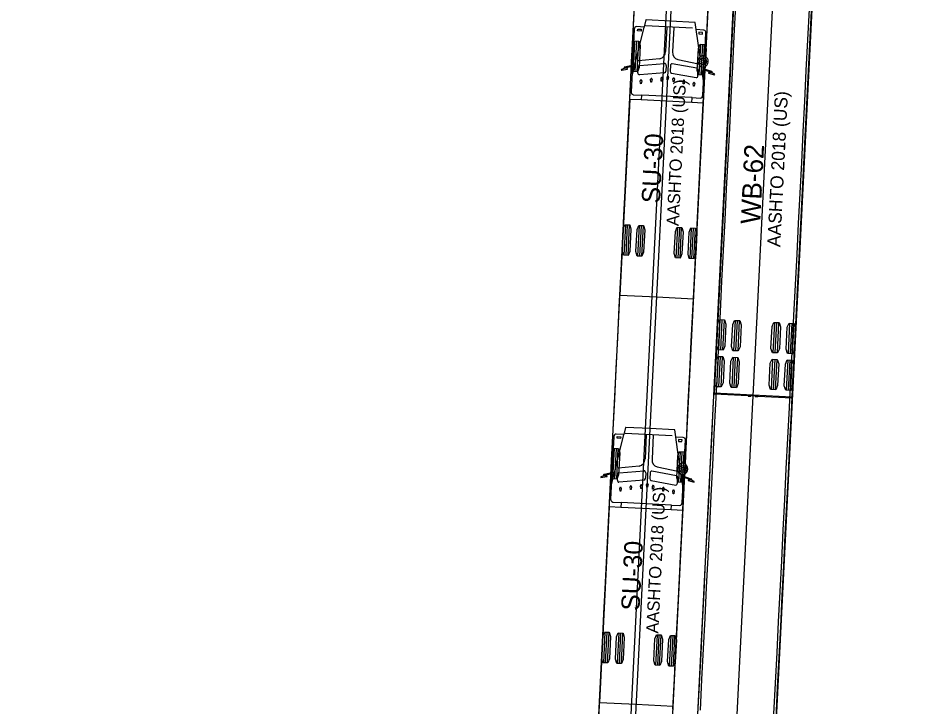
# Model space of a CAD drawing. Extents: x 260275 to 261282, y 610916 to 614143.
# Drawn here: x 260986.2 to 261084.3, y 612243.5 to 612318.4 of the extents above; entities that cross this region are included whole.
import ezdxf

# ---------------------------------------------------------------- set-up
doc = ezdxf.new("R2010")
doc.units = 0
doc.layers.add('GE_X_Alignment', color=7, linetype='Continuous')
doc.layers.add('TopoDOT_Transients', color=7, linetype='Continuous')

msp = doc.modelspace()

# ---------------------------------------------------------------- linework, layer by layer
at = {"layer": 'GE_X_Alignment'}
msp.add_line((260986.249, 610915.954), (261148.276, 614142.838), dxfattribs=at)
at = {"layer": 'TopoDOT_Transients'}
for p, q in [((261059.045, 612136.423), (261081.046, 612574.591)), ((261048.059, 612136.974), (261068.197, 612538.052)), ((261052.939, 612311.94), (261054.28, 612317.407)), ((261059.534, 612317.267), (261054.436, 612317.523)), ((261056.735, 612317.407), (261056.601, 612314.742)), ((261053.569, 612316.987), (261053.578, 612317.181)), ((261053.947, 612316.968), (261053.569, 612316.987)), ((261053.578, 612317.181), (261053.956, 612317.162)), ((261053.956, 612317.162), (261053.947, 612316.968)), ((261057.5, 612317.369), (261057.366, 612314.704)), ((261060.361, 612314.157), (261059.943, 612317.123)), ((261060.24, 612316.846), (261060.23, 612316.652)), ((261060.23, 612316.652), (261060.609, 612316.633)), ((261060.618, 612316.827), (261060.24, 612316.846)), ((261060.609, 612316.633), (261060.618, 612316.827)), ((261060.865, 612314.248), (261060.991, 612316.767)), ((261053.247, 612315.902), (261053.079, 612312.573)), ((261053.455, 612315.892), (261053.287, 612312.563)), ((261053.663, 612315.881), (261053.496, 612312.552)), ((261060.404, 612315.543), (261060.237, 612312.214)), ((261060.612, 612315.532), (261060.445, 612312.203)), ((261060.82, 612315.522), (261060.653, 612312.193)), ((261055.963, 612313.966), (261053.685, 612313.735)), ((261057.924, 612313.868), (261060.179, 612313.407)), ((261053.599, 612312.426), (261053.63, 612313.042)), ((261053.791, 612313.236), (261056.5, 612313.452)), ((261056.671, 612313.242), (261056.64, 612312.626)), ((261057.146, 612313.218), (261057.115, 612312.602)), ((261060.011, 612312.924), (261057.338, 612313.41)), ((261060.122, 612312.099), (261060.152, 612312.715)), ((261060.729, 612311.549), (261060.513, 612313.082)), ((261056.479, 612312.431), (261053.77, 612312.215)), ((261053.882, 612311.256), (261053.861, 612311.557)), ((261054.015, 612311.549), (261053.965, 612311.252)), ((261055.008, 612311.41), (261054.987, 612311.725)), ((261055.142, 612311.717), (261055.091, 612311.406)), ((261056.133, 612311.536), (261056.113, 612311.837)), ((261056.216, 612311.532), (261056.133, 612311.536)), ((261056.267, 612311.83), (261056.216, 612311.532)), ((261056.789, 612311.672), (261056.768, 612311.973)), ((261056.872, 612311.667), (261056.789, 612311.672)), ((261056.923, 612311.965), (261056.872, 612311.667)), ((261057.257, 612312.392), (261059.93, 612311.906)), ((261057.428, 612311.471), (261057.407, 612311.772)), ((261057.562, 612311.765), (261057.511, 612311.467)), ((261058.535, 612311.233), (261058.514, 612311.534)), ((261053.965, 612311.252), (261053.882, 612311.256)), ((261055.091, 612311.406), (261055.008, 612311.41)), ((261057.511, 612311.467), (261057.428, 612311.471)), ((261058.617, 612311.229), (261058.535, 612311.233)), ((261058.668, 612311.526), (261058.617, 612311.229)), ((261059.64, 612310.967), (261059.619, 612311.268)), ((261059.723, 612310.963), (261059.64, 612310.967)), ((261059.773, 612311.26), (261059.723, 612310.963)), ((261059.483, 612309.733), (261053.998, 612310.009)), ((261059.456, 612309.202), (261053.971, 612309.478)), ((261052.244, 612295.927), (261052.076, 612292.598)), ((261052.452, 612295.917), (261052.285, 612292.588)), ((261052.66, 612295.906), (261052.493, 612292.577)), ((261053.742, 612295.852), (261053.575, 612292.523)), ((261053.95, 612295.842), (261053.783, 612292.513)), ((261054.158, 612295.831), (261053.991, 612292.502)), ((261057.903, 612295.643), (261057.736, 612292.314)), ((261058.111, 612295.633), (261057.944, 612292.304)), ((261058.319, 612295.622), (261058.152, 612292.293)), ((261059.401, 612295.568), (261059.234, 612292.239)), ((261059.609, 612295.557), (261059.442, 612292.228)), ((261059.817, 612295.547), (261059.65, 612292.218)), ((261062.51, 612285.611), (261062.345, 612282.316)), ((261062.739, 612285.6), (261062.573, 612282.304)), ((261062.968, 612285.589), (261062.802, 612282.293)), ((261064.158, 612285.529), (261063.992, 612282.233)), ((261064.387, 612285.517), (261064.221, 612282.221)), ((261064.616, 612285.506), (261064.45, 612282.21)), ((261068.436, 612285.314), (261068.27, 612282.018)), ((261068.665, 612285.302), (261068.499, 612282.007)), ((261068.894, 612285.291), (261068.728, 612281.995)), ((261070.084, 612285.231), (261069.918, 612281.935)), ((261070.313, 612285.22), (261070.147, 612281.924)), ((261070.542, 612285.208), (261070.376, 612281.912)), ((261062.309, 612281.617), (261062.144, 612278.321)), ((261062.538, 612281.605), (261062.373, 612278.309)), ((261062.767, 612281.594), (261062.602, 612278.298)), ((261063.957, 612281.534), (261063.792, 612278.238)), ((261064.186, 612281.522), (261064.021, 612278.226)), ((261064.415, 612281.511), (261064.25, 612278.215)), ((261068.235, 612281.319), (261068.07, 612278.023)), ((261068.464, 612281.307), (261068.299, 612278.012)), ((261068.693, 612281.296), (261068.528, 612278)), ((261069.883, 612281.236), (261069.718, 612277.94)), ((261070.112, 612281.225), (261069.947, 612277.929)), ((261070.341, 612281.213), (261070.175, 612277.917)), ((261070.369, 612277.198), (261061.88, 612277.624)), ((261065.855, 612277.354), (261065.59, 612277.367)), ((261065.861, 612277.354), (261066.384, 612277.327)), ((261066.121, 612277.341), (261066.124, 612277.411)), ((261066.651, 612277.314), (261066.386, 612277.327)), ((261050.716, 612267.672), (261052.057, 612273.139)), ((261051.346, 612272.718), (261051.355, 612272.912)), ((261051.724, 612272.699), (261051.346, 612272.718)), ((261051.355, 612272.912), (261051.734, 612272.893)), ((261051.734, 612272.893), (261051.724, 612272.699)), ((261057.311, 612272.998), (261052.213, 612273.254)), ((261054.512, 612273.139), (261054.379, 612270.474)), ((261055.277, 612273.1), (261055.143, 612270.436)), ((261058.139, 612269.889), (261057.72, 612272.855)), ((261058.017, 612272.578), (261058.008, 612272.384)), ((261058.008, 612272.384), (261058.386, 612272.365)), ((261058.396, 612272.559), (261058.017, 612272.578)), ((261058.386, 612272.365), (261058.396, 612272.559)), ((261058.642, 612269.98), (261058.769, 612272.499)), ((261051.024, 612271.634), (261050.857, 612268.305)), ((261051.232, 612271.623), (261051.065, 612268.294)), ((261051.44, 612271.613), (261051.273, 612268.284)), ((261058.181, 612271.274), (261058.014, 612267.945)), ((261058.389, 612271.264), (261058.222, 612267.935)), ((261058.598, 612271.254), (261058.43, 612267.924)), ((261053.74, 612269.698), (261051.462, 612269.467)), ((261055.701, 612269.6), (261057.956, 612269.139)), ((261051.376, 612268.158), (261051.407, 612268.774)), ((261051.569, 612268.968), (261054.277, 612269.184)), ((261054.449, 612268.973), (261054.418, 612268.357)), ((261054.923, 612268.949), (261054.893, 612268.333)), ((261057.788, 612268.656), (261055.115, 612269.142)), ((261057.899, 612267.83), (261057.93, 612268.446)), ((261058.507, 612267.28), (261058.29, 612268.814)), ((261054.256, 612268.163), (261051.547, 612267.947)), ((261052.786, 612267.142), (261052.765, 612267.457)), ((261052.919, 612267.449), (261052.868, 612267.138)), ((261053.911, 612267.268), (261053.89, 612267.569)), ((261054.044, 612267.561), (261053.993, 612267.264)), ((261054.567, 612267.403), (261054.546, 612267.705)), ((261054.7, 612267.697), (261054.649, 612267.399)), ((261055.034, 612268.124), (261057.707, 612267.638)), ((261055.205, 612267.203), (261055.185, 612267.504)), ((261055.339, 612267.496), (261055.288, 612267.199)), ((261051.659, 612266.988), (261051.638, 612267.289)), ((261051.742, 612266.983), (261051.659, 612266.988)), ((261051.793, 612267.281), (261051.742, 612266.983)), ((261052.868, 612267.138), (261052.786, 612267.142)), ((261053.993, 612267.264), (261053.911, 612267.268)), ((261054.649, 612267.399), (261054.567, 612267.403)), ((261055.288, 612267.199), (261055.205, 612267.203)), ((261056.312, 612266.965), (261056.291, 612267.266)), ((261056.395, 612266.96), (261056.312, 612266.965)), ((261056.445, 612267.258), (261056.395, 612266.96)), ((261057.417, 612266.698), (261057.397, 612267)), ((261057.5, 612266.694), (261057.417, 612266.698)), ((261057.551, 612266.992), (261057.5, 612266.694)), ((261057.26, 612265.465), (261051.775, 612265.74)), ((261057.233, 612264.934), (261051.748, 612265.209)), ((261050.021, 612251.659), (261049.854, 612248.33)), ((261050.229, 612251.649), (261050.062, 612248.319)), ((261050.437, 612251.638), (261050.27, 612248.309)), ((261051.519, 612251.584), (261051.352, 612248.255)), ((261051.727, 612251.573), (261051.56, 612248.244)), ((261051.935, 612251.563), (261051.768, 612248.234)), ((261055.68, 612251.375), (261055.513, 612248.046)), ((261055.888, 612251.364), (261055.721, 612248.035)), ((261056.096, 612251.354), (261055.929, 612248.025)), ((261057.178, 612251.3), (261057.011, 612247.97)), ((261057.387, 612251.289), (261057.219, 612247.96)), ((261057.595, 612251.279), (261057.427, 612247.95))]:
    msp.add_line(p, q, dxfattribs=at)
for points in [[(261051.548, 612071.863), (261074.206, 612523.277)], [(261082.631, 612521.243), (261060.03, 612071.291)], [(261042.767, 612111.356), (261063.016, 612514.614)], [(261070.923, 612512.551), (261050.75, 612110.806), (261042.76, 612111.207), (261042.767, 612111.356), (261042.767, 612111.356)], [(261070.343, 612277.129), (261070.365, 612277.127), (261072.769, 612324.997), (261068.524, 612325.21), (261064.28, 612325.423), (261061.876, 612277.554), (261061.898, 612277.553)], [(261049.244, 612240.352), (261049.412, 612243.681), (261049.579, 612247.009), (261049.746, 612250.338), (261049.913, 612253.666), (261050.08, 612256.995), (261050.247, 612260.323), (261050.414, 612263.651), (261050.582, 612266.98), (261050.749, 612270.308), (261050.916, 612273.637), (261051.083, 612276.965), (261051.25, 612280.294), (261051.417, 612283.622), (261051.584, 612286.951), (261051.751, 612290.279), (261051.919, 612293.608), (261052.086, 612296.936), (261052.253, 612300.264), (261052.42, 612303.593), (261052.587, 612306.921), (261052.754, 612310.25), (261052.921, 612313.578), (261053.088, 612316.907), (261053.256, 612320.235)], [(261049.245, 612240.357), (261049.412, 612243.685), (261049.579, 612247.013), (261049.746, 612250.342), (261049.913, 612253.67), (261050.08, 612256.999), (261050.247, 612260.327), (261050.415, 612263.656), (261050.582, 612266.984), (261050.749, 612270.313), (261050.916, 612273.641), (261051.083, 612276.969), (261051.25, 612280.298), (261051.417, 612283.626), (261051.584, 612286.955), (261051.752, 612290.283), (261051.919, 612293.612), (261052.086, 612296.94), (261052.253, 612300.269), (261052.42, 612303.597), (261052.587, 612306.925), (261052.754, 612310.254), (261052.921, 612313.582), (261053.089, 612316.911), (261053.256, 612320.239)], [(261057.402, 612243.284), (261057.569, 612246.612), (261057.736, 612249.941), (261057.903, 612253.269), (261058.07, 612256.598), (261058.237, 612259.926), (261058.405, 612263.254), (261058.572, 612266.583), (261058.739, 612269.911), (261058.906, 612273.24), (261059.073, 612276.568), (261059.24, 612279.897), (261059.407, 612283.225), (261059.574, 612286.554), (261059.742, 612289.882), (261059.909, 612293.21), (261060.076, 612296.539), (261060.243, 612299.867), (261060.41, 612303.196), (261060.577, 612306.524), (261060.744, 612309.853), (261060.911, 612313.181), (261061.079, 612316.51), (261061.246, 612319.838)], [(261057.402, 612243.28), (261057.569, 612246.608), (261057.736, 612249.937), (261057.903, 612253.265), (261058.07, 612256.593), (261058.237, 612259.922), (261058.404, 612263.25), (261058.571, 612266.579), (261058.739, 612269.907), (261058.906, 612273.236), (261059.073, 612276.564), (261059.24, 612279.893), (261059.407, 612283.221), (261059.574, 612286.549), (261059.741, 612289.878), (261059.908, 612293.206), (261060.076, 612296.535), (261060.243, 612299.863), (261060.41, 612303.192), (261060.577, 612306.52), (261060.744, 612309.849), (261060.911, 612313.177), (261061.078, 612316.505), (261061.245, 612319.834)], [(261060.4, 612243.169), (261060.567, 612246.498), (261060.734, 612249.828), (261060.901, 612253.157), (261061.068, 612256.487), (261061.236, 612259.816), (261061.403, 612263.146), (261061.57, 612266.475), (261061.737, 612269.805), (261061.904, 612273.134), (261062.072, 612276.464), (261062.239, 612279.793), (261062.406, 612283.123), (261062.573, 612286.453), (261062.74, 612289.782), (261062.907, 612293.112), (261063.075, 612296.441), (261063.242, 612299.771), (261063.409, 612303.1), (261063.576, 612306.43), (261063.743, 612309.759), (261063.911, 612313.089), (261064.078, 612316.418), (261064.245, 612319.748)], [(261060.125, 612242.689), (261060.293, 612246.019), (261060.46, 612249.348), (261060.627, 612252.678), (261060.794, 612256.007), (261060.961, 612259.337), (261061.128, 612262.666), (261061.296, 612265.996), (261061.463, 612269.325), (261061.63, 612272.655), (261061.797, 612275.984), (261061.964, 612279.314), (261062.132, 612282.643), (261062.299, 612285.973), (261062.466, 612289.303), (261062.633, 612292.632), (261062.8, 612295.962), (261062.967, 612299.291), (261063.135, 612302.621), (261063.302, 612305.95), (261063.469, 612309.28), (261063.636, 612312.609), (261063.803, 612315.939), (261063.971, 612319.268)], [(261068.39, 612242.767), (261068.557, 612246.097), (261068.724, 612249.426), (261068.891, 612252.756), (261069.058, 612256.085), (261069.226, 612259.415), (261069.393, 612262.745), (261069.56, 612266.074), (261069.727, 612269.404), (261069.894, 612272.733), (261070.062, 612276.063), (261070.229, 612279.392), (261070.396, 612282.722), (261070.563, 612286.051), (261070.73, 612289.381), (261070.897, 612292.71), (261071.065, 612296.04), (261071.232, 612299.37), (261071.399, 612302.699), (261071.566, 612306.029), (261071.733, 612309.358), (261071.901, 612312.688), (261072.068, 612316.017), (261072.235, 612319.347)], [(261068.615, 612242.263), (261068.782, 612245.592), (261068.949, 612248.922), (261069.116, 612252.251), (261069.283, 612255.581), (261069.451, 612258.91), (261069.618, 612262.24), (261069.785, 612265.57), (261069.952, 612268.899), (261070.119, 612272.229), (261070.286, 612275.558), (261070.454, 612278.888), (261070.621, 612282.217), (261070.788, 612285.547), (261070.955, 612288.876), (261071.122, 612292.206), (261071.29, 612295.535), (261071.457, 612298.865), (261071.624, 612302.194), (261071.791, 612305.524), (261071.958, 612308.854), (261072.125, 612312.183), (261072.293, 612315.513), (261072.46, 612318.842)], [(261060.753, 612317.082), (261059.947, 612317.123), (261059.942, 612317.128), (261059.833, 612317.906), (261059.791, 612317.91), (261057.15, 612318.042), (261054.51, 612318.175), (261054.468, 612318.175), (261054.281, 612317.412), (261054.276, 612317.408), (261053.47, 612317.448)], [(261053.201, 612317.158), (261053.004, 612313.23), (261052.997, 612313.219), (261052.155, 612313.034), (261052.154, 612313.034)], [(261052.11, 612312.963), (261052.107, 612312.916), (261052.106, 612312.916), (261051.805, 612312.799), (261051.802, 612312.734), (261051.805, 612312.734), (261052.467, 612312.84), (261052.47, 612312.841), (261052.473, 612312.897), (261052.47, 612312.897), (261052.154, 612312.922), (261052.153, 612312.922), (261052.156, 612312.966)], [(261052.168, 612312.986), (261052.169, 612312.986), (261052.996, 612313.164), (261053, 612313.152), (261052.861, 612310.381)], [(261060.651, 612309.99), (261060.79, 612312.761), (261060.796, 612312.773), (261061.601, 612312.512), (261061.601, 612312.512)], [(261061.62, 612312.559), (261061.619, 612312.559), (261060.8, 612312.827), (261060.794, 612312.839), (261060.806, 612313.067)], [(261061.611, 612312.492), (261061.61, 612312.447), (261061.609, 612312.447), (261061.292, 612312.454), (261061.289, 612312.454), (261061.286, 612312.399), (261061.289, 612312.397), (261061.937, 612312.225), (261061.94, 612312.225), (261061.944, 612312.29), (261061.656, 612312.436), (261061.655, 612312.437), (261061.657, 612312.484)], [(261053.1, 612310.054), (261053.994, 612310.009), (261053.997, 612310.005), (261053.971, 612309.479), (261053.96, 612309.478), (261052.719, 612309.541), (261051.651, 612288.281), (261055.646, 612288.08), (261059.641, 612287.879), (261060.708, 612309.139), (261059.467, 612309.202), (261059.456, 612309.203), (261059.482, 612309.729), (261059.486, 612309.733), (261060.381, 612309.688)], [(261061.922, 612277.551), (261061.923, 612277.551), (261065.554, 612277.369), (261065.59, 612277.367), (261065.587, 612277.297), (261065.588, 612277.297), (261065.854, 612277.283)], [(261066.38, 612277.257), (261066.646, 612277.244), (261066.648, 612277.244), (261066.651, 612277.314), (261066.687, 612277.312), (261070.318, 612277.13), (261070.319, 612277.13)], [(261058.531, 612272.814), (261057.724, 612272.855), (261057.72, 612272.859), (261057.61, 612273.637), (261057.568, 612273.642), (261054.928, 612273.774), (261052.287, 612273.907), (261052.245, 612273.907), (261052.058, 612273.144), (261052.053, 612273.139), (261051.247, 612273.18)], [(261050.978, 612272.89), (261050.781, 612268.962), (261050.774, 612268.95), (261049.932, 612268.766), (261049.931, 612268.766)], [(261049.887, 612268.695), (261049.884, 612268.648), (261049.884, 612268.647), (261049.583, 612268.531), (261049.579, 612268.466), (261049.582, 612268.466), (261050.244, 612268.572), (261050.247, 612268.573), (261050.25, 612268.629), (261050.248, 612268.629), (261049.931, 612268.653), (261049.931, 612268.654), (261049.933, 612268.698)], [(261049.946, 612268.718), (261049.946, 612268.718), (261050.773, 612268.896), (261050.777, 612268.884), (261050.638, 612266.113)], [(261058.428, 612265.722), (261058.567, 612268.493), (261058.573, 612268.504), (261059.378, 612268.244), (261059.378, 612268.244)], [(261059.398, 612268.291), (261059.397, 612268.291), (261058.577, 612268.558), (261058.571, 612268.571), (261058.583, 612268.798)], [(261059.388, 612268.223), (261059.387, 612268.179), (261059.386, 612268.179), (261059.069, 612268.186), (261059.066, 612268.186), (261059.064, 612268.13), (261059.067, 612268.129), (261059.715, 612267.957), (261059.717, 612267.957), (261059.721, 612268.022), (261059.433, 612268.168), (261059.433, 612268.168), (261059.434, 612268.216)], [(261050.877, 612265.785), (261051.772, 612265.74), (261051.775, 612265.737), (261051.748, 612265.21), (261051.737, 612265.21), (261050.496, 612265.272), (261049.428, 612244.012), (261053.423, 612243.812), (261057.418, 612243.611), (261058.486, 612264.871), (261057.244, 612264.933), (261057.233, 612264.935), (261057.26, 612265.461), (261057.263, 612265.465), (261058.158, 612265.42)]]:
    msp.add_lwpolyline(points, dxfattribs=at)
for points in [[(261053.195, 612315.905), (261053.714, 612315.879), (261053.847, 612315.405), (261053.727, 612313.008), (261053.547, 612312.55), (261053.028, 612312.576), (261052.895, 612313.05), (261053.015, 612315.447)], [(261060.353, 612315.545), (261060.872, 612315.519), (261061.005, 612315.045), (261060.885, 612312.648), (261060.705, 612312.19), (261060.185, 612312.216), (261060.052, 612312.69), (261060.173, 612315.087)], [(261052.192, 612295.93), (261052.711, 612295.904), (261052.844, 612295.43), (261052.724, 612293.033), (261052.544, 612292.575), (261052.025, 612292.601), (261051.892, 612293.075), (261052.012, 612295.472)], [(261053.69, 612295.855), (261054.209, 612295.829), (261054.343, 612295.355), (261054.222, 612292.958), (261054.042, 612292.499), (261053.523, 612292.526), (261053.39, 612292.999), (261053.51, 612295.396)], [(261057.852, 612295.646), (261058.371, 612295.62), (261058.504, 612295.146), (261058.384, 612292.749), (261058.204, 612292.291), (261057.684, 612292.317), (261057.551, 612292.791), (261057.672, 612295.188)], [(261059.35, 612295.571), (261059.869, 612295.544), (261060.002, 612295.071), (261059.882, 612292.674), (261059.702, 612292.215), (261059.182, 612292.241), (261059.049, 612292.715), (261059.17, 612295.112)], [(261062.453, 612285.614), (261063.025, 612285.586), (261063.173, 612285.116), (261063.054, 612282.743), (261062.859, 612282.29), (261062.288, 612282.319), (261062.139, 612282.789), (261062.258, 612285.162)], [(261064.101, 612285.532), (261064.672, 612285.503), (261064.821, 612285.033), (261064.702, 612282.66), (261064.507, 612282.207), (261063.936, 612282.236), (261063.787, 612282.706), (261063.906, 612285.079)], [(261068.379, 612285.317), (261068.95, 612285.288), (261069.099, 612284.818), (261068.98, 612282.445), (261068.785, 612281.992), (261068.214, 612282.021), (261068.065, 612282.491), (261068.184, 612284.864)], [(261070.027, 612285.234), (261070.598, 612285.205), (261070.747, 612284.735), (261070.628, 612282.362), (261070.433, 612281.91), (261069.862, 612281.938), (261069.713, 612282.408), (261069.832, 612284.781)], [(261062.253, 612281.619), (261062.824, 612281.591), (261062.973, 612281.121), (261062.854, 612278.748), (261062.658, 612278.295), (261062.087, 612278.324), (261061.938, 612278.794), (261062.057, 612281.167)], [(261063.901, 612281.537), (261064.472, 612281.508), (261064.621, 612281.038), (261064.502, 612278.665), (261064.306, 612278.212), (261063.735, 612278.241), (261063.586, 612278.711), (261063.705, 612281.084)], [(261068.179, 612281.322), (261068.75, 612281.293), (261068.899, 612280.823), (261068.78, 612278.45), (261068.584, 612277.997), (261068.013, 612278.026), (261067.864, 612278.496), (261067.983, 612280.869)], [(261069.826, 612281.239), (261070.398, 612281.21), (261070.547, 612280.74), (261070.428, 612278.367), (261070.232, 612277.915), (261069.661, 612277.943), (261069.512, 612278.413), (261069.631, 612280.786)], [(261050.972, 612271.636), (261051.492, 612271.61), (261051.625, 612271.136), (261051.504, 612268.739), (261051.324, 612268.281), (261050.805, 612268.307), (261050.672, 612268.781), (261050.792, 612271.178)], [(261058.13, 612271.277), (261058.649, 612271.251), (261058.782, 612270.777), (261058.662, 612268.38), (261058.482, 612267.922), (261057.963, 612267.948), (261057.83, 612268.422), (261057.95, 612270.819)], [(261049.969, 612251.662), (261050.489, 612251.636), (261050.622, 612251.162), (261050.501, 612248.765), (261050.321, 612248.306), (261049.802, 612248.332), (261049.669, 612248.806), (261049.789, 612251.203)], [(261051.467, 612251.586), (261051.987, 612251.56), (261052.12, 612251.086), (261051.999, 612248.689), (261051.82, 612248.231), (261051.3, 612248.257), (261051.167, 612248.731), (261051.287, 612251.128)], [(261055.629, 612251.377), (261056.148, 612251.351), (261056.281, 612250.877), (261056.161, 612248.48), (261055.981, 612248.022), (261055.462, 612248.048), (261055.329, 612248.522), (261055.449, 612250.919)], [(261057.127, 612251.302), (261057.646, 612251.276), (261057.779, 612250.802), (261057.659, 612248.405), (261057.479, 612247.947), (261056.96, 612247.973), (261056.827, 612248.447), (261056.947, 612250.844)]]:
    msp.add_lwpolyline(points, close=True, dxfattribs=at)
for centre, radius in [((261060.69, 612313.665), 0.374), ((261060.69, 612313.665), 0.193), ((261061.908, 612277.518), 0.0266), ((261070.329, 612277.095), 0.0266), ((261058.468, 612269.396), 0.374), ((261058.468, 612269.396), 0.193)]:
    msp.add_circle(centre, radius, dxfattribs=at)
for centre, radius, start, end in [((261053.483, 612317.167), 0.282, 92.67391, 181.75333), ((261060.712, 612316.804), 0.282, 352.49767, 81.5771), ((261055.829, 612314.728), 0.773, 280.01597, 1.10013), ((261058.134, 612314.612), 0.773, 173.15088, 254.23504), ((261060.759, 612313.654), 0.63, 176.4803, 228.88311), ((261060.759, 612313.669), 0.629, 129.17109, 177.86038), ((261060.694, 612313.751), 0.526, 71.07067, 129.31667), ((261060.623, 612313.668), 0.628, 286.8788, 67.3705), ((261052.133, 612312.998), 0.0418, 59.61742, 236.63235), ((261052.127, 612312.998), 0.0434, 312.53921, 343.21198), ((261053.822, 612313.046), 0.193, 99.26792, 181.18241), ((261056.448, 612312.622), 0.193, 279.26299, 1.18734), ((261056.489, 612313.268), 0.184, 351.66723, 86.52737), ((261057.307, 612312.578), 0.193, 173.06366, 254.98801), ((261057.331, 612313.226), 0.184, 87.72364, 182.58377), ((261059.961, 612312.738), 0.193, 353.06859, 74.98308), ((261060.686, 612313.578), 0.524, 229.38452, 283.18459), ((261061.644, 612312.521), 0.0434, 191.03902, 221.7118), ((261061.638, 612312.521), 0.0418, 297.61865, 114.63358), ((261053.781, 612312.399), 0.184, 171.66167, 266.53293), ((261053.951, 612311.571), 0.091, 94.64508, 188.80895), ((261053.927, 612311.572), 0.0909, 345.40639, 79.64159), ((261055.078, 612311.725), 0.091, 94.64508, 188.80895), ((261055.054, 612311.726), 0.0909, 345.40639, 79.64159), ((261056.202, 612311.851), 0.091, 94.64508, 188.80895), ((261056.179, 612311.852), 0.0909, 345.40639, 79.64159), ((261056.858, 612311.987), 0.091, 94.64508, 188.80895), ((261056.835, 612311.988), 0.091, 345.44206, 79.60593), ((261057.497, 612311.786), 0.0909, 94.60942, 188.84462), ((261057.474, 612311.787), 0.091, 345.44206, 79.60593), ((261058.604, 612311.548), 0.0909, 94.60942, 188.84462), ((261058.58, 612311.549), 0.091, 345.44206, 79.60593), ((261059.937, 612312.09), 0.184, 267.71808, 2.58934), ((261059.709, 612311.282), 0.0909, 94.60942, 188.84462), ((261059.685, 612311.283), 0.091, 345.44206, 79.60593), ((261053.183, 612310.365), 0.323, 177.1255, 254.97391), ((261060.329, 612310.007), 0.323, 279.2771, 357.1255), ((261061.908, 612277.518), 0.0363, 106.20231, 67.36494), ((261065.856, 612277.319), 0.0352, 86.91304, 269.55244), ((261065.856, 612277.319), 0.0352, 267.14108, 87.72757), ((261066.382, 612277.292), 0.0352, 86.52344, 267.10992), ((261066.382, 612277.292), 0.0354, 271.41704, 83.6025), ((261070.329, 612277.095), 0.0363, 106.88607, 68.0487), ((261051.26, 612272.898), 0.282, 92.67391, 181.75333), ((261058.489, 612272.535), 0.282, 352.49767, 81.5771), ((261053.606, 612270.459), 0.773, 280.01597, 1.10013), ((261055.911, 612270.344), 0.773, 173.15088, 254.23504), ((261058.536, 612269.386), 0.63, 176.4803, 228.88311), ((261058.536, 612269.401), 0.629, 129.17109, 177.86038), ((261058.472, 612269.482), 0.526, 71.07067, 129.31667), ((261058.4, 612269.4), 0.628, 286.8788, 67.3705), ((261049.91, 612268.73), 0.0418, 59.61742, 236.63235), ((261049.904, 612268.73), 0.0434, 312.53921, 343.21198), ((261051.6, 612268.778), 0.193, 99.26792, 181.18241), ((261054.266, 612269), 0.184, 351.66723, 86.52737), ((261055.108, 612268.958), 0.184, 87.72364, 182.58377), ((261057.738, 612268.47), 0.193, 353.06859, 74.98308), ((261058.463, 612269.309), 0.524, 229.38452, 283.18459), ((261051.559, 612268.131), 0.184, 171.66167, 266.53293), ((261052.855, 612267.457), 0.091, 94.64508, 188.80895), ((261052.831, 612267.458), 0.0909, 345.40639, 79.64159), ((261053.98, 612267.583), 0.091, 94.64508, 188.80895), ((261053.956, 612267.584), 0.0909, 345.40639, 79.64159), ((261054.225, 612268.353), 0.193, 279.26299, 1.18734), ((261054.636, 612267.718), 0.091, 94.64508, 188.80895), ((261054.612, 612267.72), 0.091, 345.44206, 79.60593), ((261055.084, 612268.31), 0.193, 173.06366, 254.98801), ((261055.274, 612267.518), 0.0909, 94.60942, 188.84462), ((261055.251, 612267.519), 0.091, 345.44206, 79.60593), ((261057.715, 612267.822), 0.184, 267.71808, 2.58934), ((261059.421, 612268.252), 0.0434, 191.03902, 221.7118), ((261059.415, 612268.253), 0.0418, 297.61865, 114.63358), ((261051.728, 612267.303), 0.091, 94.64508, 188.80895), ((261051.705, 612267.304), 0.0909, 345.40639, 79.64159), ((261056.381, 612267.28), 0.0909, 94.60942, 188.84462), ((261056.357, 612267.281), 0.091, 345.44206, 79.60593), ((261057.486, 612267.014), 0.0909, 94.60942, 188.84462), ((261057.463, 612267.015), 0.091, 345.44206, 79.60593), ((261050.96, 612266.097), 0.323, 177.1255, 254.97391), ((261058.106, 612265.738), 0.323, 279.2771, 357.1255)]:
    msp.add_arc(centre, radius, start, end, dxfattribs=at)

# ---------------------------------------------------------------- texts
for s, height, p in [('AASHTO 2018 (US)', 1.33333, (261058.041, 612295.755)), ('AASHTO 2018 (US)', 1.41667, (261069.066, 612293.477)), ('SU-30', 2, (261055.995, 612298.218)), ('WB-62', 2.125, (261066.884, 612295.943)), ('AASHTO 2018 (US)', 1.33333, (261055.818, 612251.487)), ('SU-30', 2, (261053.772, 612253.95))]:
    msp.add_text(s, height=height, rotation=87.1255, dxfattribs=at).set_placement(p)

doc.saveas('drawing.dxf')
